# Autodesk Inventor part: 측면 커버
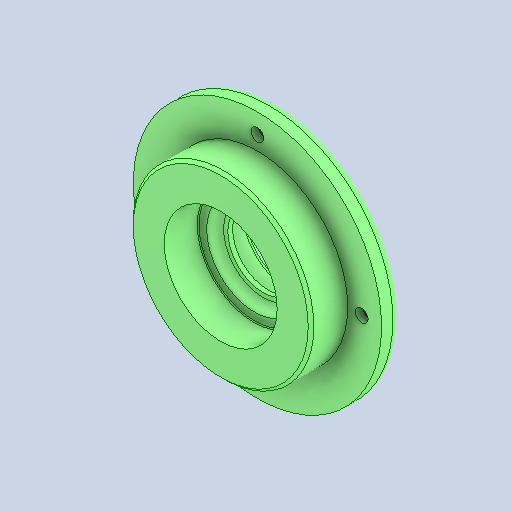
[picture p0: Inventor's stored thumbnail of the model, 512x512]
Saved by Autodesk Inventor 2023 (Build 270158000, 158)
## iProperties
Created: 2025-04
Part Number: 측면 커버
Material: 알루미늄 6061
Document SubType Name: Modeling
Designer: user
Density: 2.71 g/cm^3
Appearance: 기본값
Company: 한국ATC센터
Author: jhkim
Revision Number: 1
Sending System: Autodesk Inventor 2026
Preprocessor: ST-DEVELOPER v20.1
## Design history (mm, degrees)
feature "솔리드1"
node "솔리드2"
